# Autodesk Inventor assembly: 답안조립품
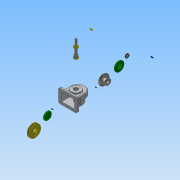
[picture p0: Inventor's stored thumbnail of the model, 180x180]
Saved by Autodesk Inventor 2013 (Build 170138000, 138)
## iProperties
Created: 2017-11
Part Number: 답안조립품
Document SubType Name: Assembly
Designer: Administrator
Author: Administrator
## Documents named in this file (14)
- C:\Users\Administrator\Desktop\471108V1028\답안조립품.iam
- C:\Users\Administrator\Desktop\471108V1028\V-벨트풀리.ipt
- C:\Users\Administrator\Desktop\471108V1028\뒤커버.ipt
- C:\Users\Administrator\Desktop\471108V1028\멈춤나사 - M4 x 10.ipt
- 멈춤나사 - M4 x 10.ipt
- C:\Users\Administrator\Desktop\471108V1028\베어링 6002.ipt
- C:\Users\Administrator\Desktop\471108V1028\본체.ipt
- C:\Users\Administrator\Desktop\471108V1028\볼트 M3 x 8.ipt
- C:\Users\Administrator\Desktop\471108V1028\스퍼기어.ipt
- C:\Users\Administrator\Desktop\471108V1028\앞커버.ipt
- C:\Users\Administrator\Desktop\471108V1028\오일 실 15 30 7.ipt
- C:\Users\Administrator\Desktop\471108V1028\축.ipt
- C:\Users\Administrator\Desktop\471108V1028\키 - 5 x 5 x 18.ipt
- C:\Users\Administrator\Desktop\471108V1028\키 - 6 x 6 x 22.ipt
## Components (1 placed, 1 different names)
1. V-벨트풀리:1
